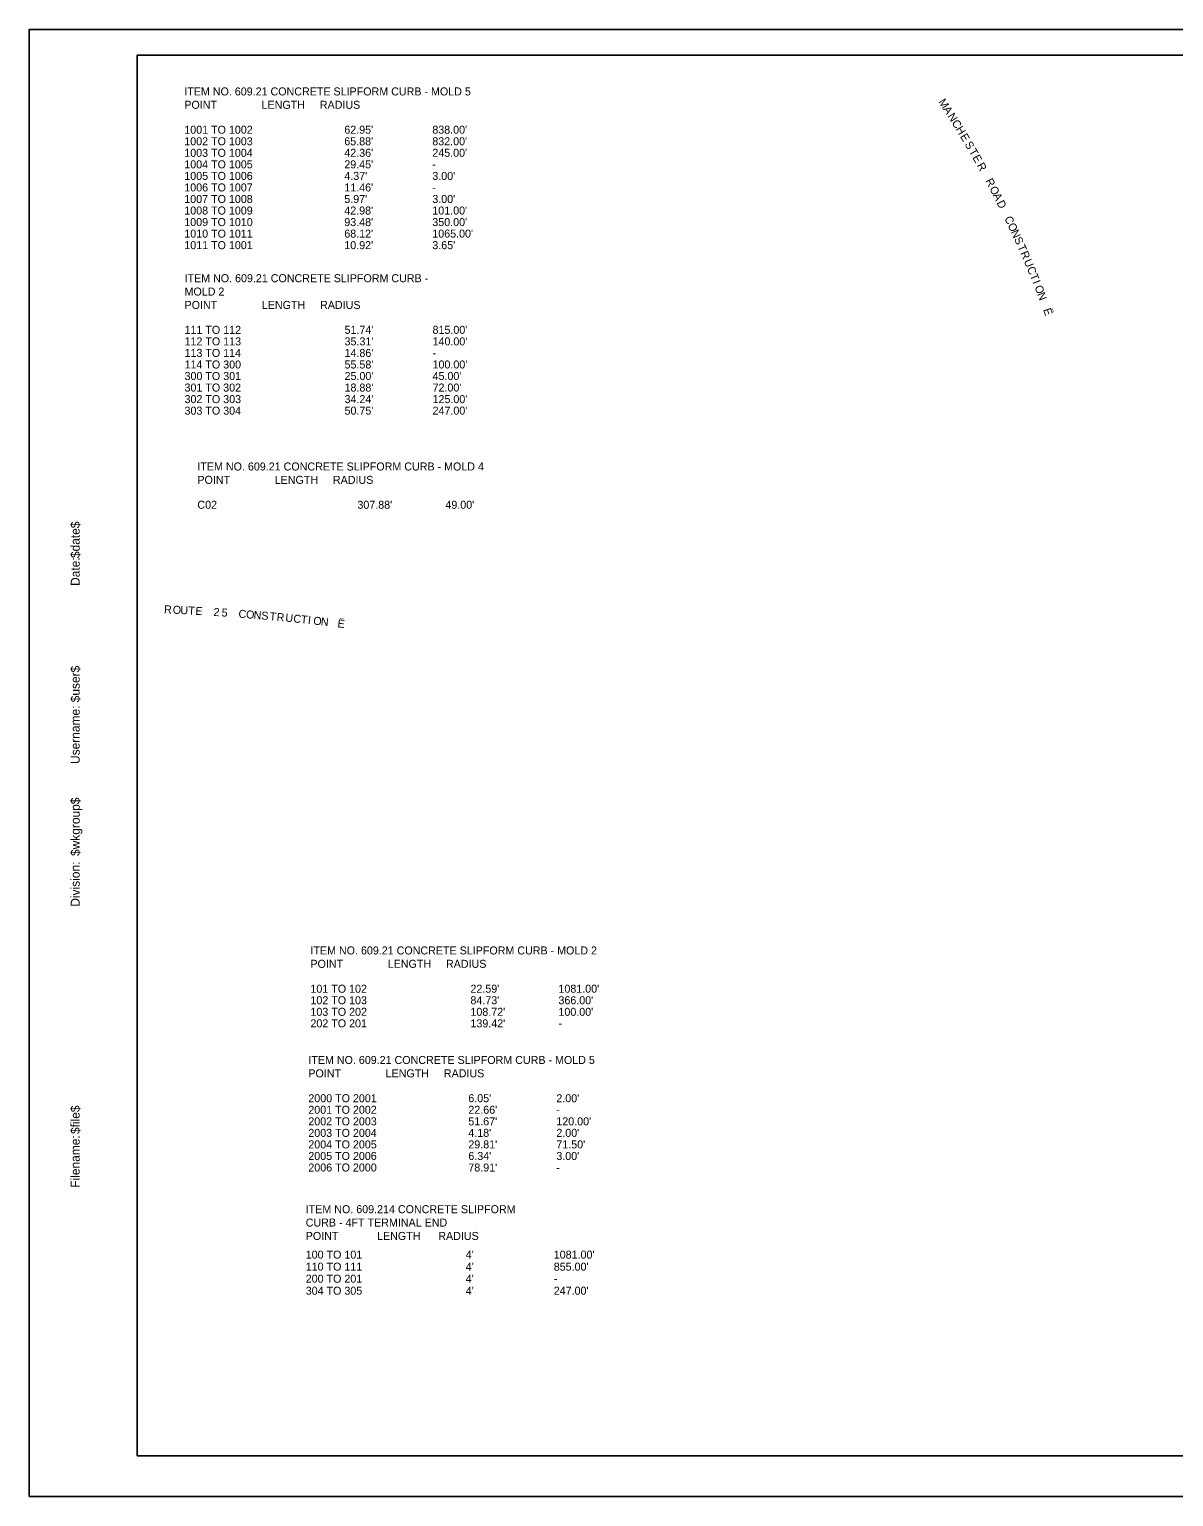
# Model space of a CAD drawing. Extents: x 916257 to 917115, y 329394 to 329944.
# Drawn here: x 916257 to 916686, y 329394 to 329944 of the extents above; entities that cross this region are included whole.
import ezdxf

# ---------------------------------------------------------------- set-up
doc = ezdxf.new("R2010")
doc.units = 0
for name, color, linetype in [('ANNOTATION', 7, 'Continuous'), ('D_Curb_Type1_Lt', 7, 'Continuous'), ('D_Roadway_Edge_Pavement', 7, 'Continuous')]:
    doc.layers.add(name, color=color, linetype=linetype)

msp = doc.modelspace()

# ---------------------------------------------------------------- linework, layer by layer
at = {"layer": 'D_Curb_Type1_Lt'}
msp.add_lwpolyline([(916257, 329393.91), (917107, 329393.91), (917107, 329943.91), (916257, 329943.91)], close=True, dxfattribs=at)
at = {"layer": 'D_Roadway_Edge_Pavement'}
for p, q in [((917097.47, 329934.21), (916297.47, 329934.21)), ((916297.47, 329934.21), (916297.47, 329409.21)), ((916297.47, 329409.21), (917097.47, 329409.21))]:
    msp.add_line(p, q, dxfattribs=at)

# ---------------------------------------------------------------- texts
at = {"layer": 'ANNOTATION'}
for s, rotation, p in [('POINT               LENGTH     RADIUS', 0.0011, (916315.11, 329914.13)), ('ITEM NO. 609.21 CONCRETE SLIPFORM CURB - MOLD 5', 0.0011, (916315.11, 329919.14)), ('M', 303.1172, (916597.75, 329916.7)), ('A', 302.6288, (916599.53, 329913.98)), ('N', 302.1668, (916601.19, 329911.38)), ('1001 TO 1002', 0.0011, (916315.11, 329904.79)), ("62.95'", 0.0011, (916375.11, 329904.79)), ("838.00'", 0.0011, (916408.11, 329904.79)), ('C', 301.7328, (916602.74, 329908.93)), ('H', 301.3073, (916604.23, 329906.52)), ('1002 TO 1003', 0.0011, (916315.11, 329900.46)), ("65.88'", 0.0011, (916375.11, 329900.46)), ("832.00'", 0.0011, (916408.11, 329900.46)), ('E', 300.8239, (916605.9, 329903.77)), ('S', 300.318, (916607.63, 329900.87)), ('1003 TO 1004', 0.0011, (916315.11, 329896.13)), ('1004 TO 1005', 0.0011, (916315.11, 329891.81)), ("42.36'", 0.0011, (916375.11, 329896.14)), ("29.45'", 0.0011, (916375.11, 329891.81)), ("245.00'", 0.0011, (916408.11, 329896.14)), ('T', 299.8525, (916609.2, 329898.19)), ('E', 299.4521, (916610.53, 329895.88)), ('1005 TO 1006', 0.0011, (916315.11, 329887.48)), ("4.37'", 0.0011, (916375.11, 329887.48)), ("3.00'", 0.0011, (916408.11, 329887.48)), ('-', 0.0011, (916408.11, 329891.81)), ('R', 298.9463, (916612.19, 329892.94)), ('1006 TO 1007', 0.0011, (916315.11, 329883.15)), ("11.46'", 0.0011, (916375.11, 329883.15)), ('-', 0.0011, (916408.11, 329883.15)), ('R', 297.9465, (916615.39, 329887.09)), ('O', 297.4567, (916616.92, 329884.21)), ('1007 TO 1008', 0.0011, (916315.11, 329878.83)), ("5.97'", 0.0011, (916375.11, 329878.83)), ("3.00'", 0.0011, (916408.11, 329878.83)), ('A', 297.0312, (916618.23, 329881.69)), ('D', 296.5692, (916619.63, 329878.95)), ('1008 TO 1009', 0.0011, (916315.11, 329874.5)), ('1009 TO 1010', 0.0011, (916315.11, 329870.17)), ("42.98'", 0.0011, (916375.11, 329874.5)), ("93.48'", 0.0011, (916375.11, 329870.17)), ("350.00'", 0.0011, (916408.11, 329870.17)), ("101.00'", 0.0011, (916408.11, 329874.5)), ('C', 295.5855, (916622.54, 329873.07)), ('1010 TO 1011', 0.0011, (916315.11, 329865.84)), ("68.12'", 0.0011, (916375.11, 329865.85)), ("1065.00'", 0.0011, (916408.11, 329865.85)), ('O', 295.16, (916623.76, 329870.51)), ('N', 294.7346, (916624.97, 329867.95)), ('1011 TO 1001', 0.0011, (916315.11, 329861.52)), ("10.92'", 0.0011, (916375.11, 329861.52)), ("3.65'", 0.0011, (916408.11, 329861.52)), ('S', 294.3005, (916626.18, 329865.32)), ('T', 293.835, (916627.46, 329862.49)), ('R', 293.4346, (916628.54, 329860.05)), ('U', 292.9448, (916629.84, 329857.05)), ('ITEM NO. 609.21 CONCRETE SLIPFORM CURB -', 0.0011, (916315.2, 329849.13)), ('C', 292.4953, (916631.01, 329854.29)), ('T', 292.0698, (916632.09, 329851.67)), ('MOLD 2', 0.0011, (916315.2, 329844.12)), ('I', 291.6694, (916633.1, 329849.2)), ('O', 291.3668, (916633.85, 329847.33)), ('N', 290.9413, (916634.88, 329844.68)), ('POINT               LENGTH     RADIUS', 0.0011, (916315.2, 329839.11)), ('Ë', 289.9974, (916637.11, 329838.8)), ('111 TO 112', 0.0011, (916315.2, 329829.78)), ("51.74'", 0.0011, (916375.2, 329829.78)), ("815.00'", 0.0011, (916408.2, 329829.78)), ('112 TO 113', 0.0011, (916315.2, 329825.45)), ('113 TO 114', 0.0011, (916315.2, 329821.12)), ("35.31'", 0.0011, (916375.2, 329825.45)), ("14.86'", 0.0011, (916375.2, 329821.12)), ("140.00'", 0.0011, (916408.2, 329825.45)), ('114 TO 300', 0.0011, (916315.2, 329816.79)), ("55.58'", 0.0011, (916375.2, 329816.79)), ('-', 0.0011, (916408.2, 329821.12)), ("100.00'", 0.0011, (916408.2, 329816.8)), ('300 TO 301', 0.0011, (916315.2, 329812.47)), ("25.00'", 0.0011, (916375.2, 329812.47)), ("45.00'", 0.0011, (916408.2, 329812.47)), ('301 TO 302', 0.0011, (916315.2, 329808.14)), ('302 TO 303', 0.0011, (916315.2, 329803.81)), ("34.24'", 0.0011, (916375.2, 329803.81)), ("18.88'", 0.0011, (916375.2, 329808.14)), ("72.00'", 0.0011, (916408.2, 329808.14)), ("125.00'", 0.0011, (916408.2, 329803.81)), ('303 TO 304', 0.0011, (916315.2, 329799.49)), ("50.75'", 0.0011, (916375.2, 329799.49)), ("247.00'", 0.0011, (916408.2, 329799.49)), ('ITEM NO. 609.21 CONCRETE SLIPFORM CURB - MOLD 4', 0.0011, (916320.02, 329778.56)), ('POINT               LENGTH     RADIUS', 0.0011, (916320.02, 329773.55)), ('C02', 0.0011, (916320.02, 329764.21)), ("307.88'", 0.0011, (916380.02, 329764.21)), ("49.00'", 0.0011, (916413.02, 329764.21)), ('R', 357.5179, (916307.46, 329725.04)), ('O', 357.2944, (916310.73, 329724.9)), ('U', 357.1002, (916313.56, 329724.77)), ('T', 356.895, (916316.55, 329724.62)), ('E', 356.7123, (916319.22, 329724.47)), ('2', 356.2487, (916325.98, 329724.07)), ('5', 356.0399, (916329.02, 329723.87)), ('C', 355.6056, (916335.35, 329723.42)), ('O', 355.4114, (916338.18, 329723.2)), ('N', 355.2172, (916341.01, 329722.98)), ('S', 355.0191, (916343.89, 329722.74)), ('T', 354.8066, (916346.98, 329722.47)), ('R', 354.6239, (916349.64, 329722.23)), ('U', 354.4004, (916352.89, 329721.92)), ('C', 354.1952, (916355.88, 329721.63)), ('T', 354.001, (916358.7, 329721.34)), ('I', 353.8183, (916361.35, 329721.07)), ('O', 353.6802, (916363.36, 329720.85)), ('N', 353.486, (916366.18, 329720.54)), ('Ë', 353.0552, (916372.43, 329719.81)), ('ITEM NO. 609.21 CONCRETE SLIPFORM CURB - MOLD 2', 0.0011, (916362.41, 329597.15)), ('POINT               LENGTH     RADIUS', 0.0011, (916362.41, 329592.14)), ('101 TO 102', 0.0011, (916362.41, 329582.8)), ('102 TO 103', 0.0011, (916362.41, 329578.48)), ("84.73'", 0.0011, (916422.41, 329578.48)), ("22.59'", 0.0011, (916422.41, 329582.81)), ("366.00'", 0.0011, (916455.41, 329578.48)), ("1081.00'", 0.0011, (916455.41, 329582.81)), ('103 TO 202', 0.0011, (916362.41, 329574.15)), ("108.72'", 0.0011, (916422.41, 329574.15)), ("100.00'", 0.0011, (916455.41, 329574.15)), ('202 TO 201', 0.0011, (916362.41, 329569.82)), ("139.42'", 0.0011, (916422.41, 329569.82)), ('-', 0.0011, (916455.41, 329569.82)), ('POINT               LENGTH     RADIUS', 0.0011, (916361.62, 329551.09)), ('ITEM NO. 609.21 CONCRETE SLIPFORM CURB - MOLD 5', 0.0011, (916361.62, 329556.1)), ('2000 TO 2001', 0.0011, (916361.62, 329541.76)), ("6.05'", 0.0011, (916421.62, 329541.76)), ("2.00'", 0.0011, (916454.62, 329541.76)), ('2001 TO 2002', 0.0011, (916361.62, 329537.43)), ("22.66'", 0.0011, (916421.62, 329537.43)), ('-', 0.0011, (916454.62, 329537.43)), ('2002 TO 2003', 0.0011, (916361.62, 329533.1)), ("51.67'", 0.0011, (916421.62, 329533.1)), ("120.00'", 0.0011, (916454.62, 329533.1)), ('2003 TO 2004', 0.0011, (916361.62, 329528.77)), ('2004 TO 2005', 0.0011, (916361.62, 329524.45)), ("4.18'", 0.0011, (916421.62, 329528.78)), ("29.81'", 0.0011, (916421.62, 329524.45)), ("2.00'", 0.0011, (916454.62, 329528.78)), ("71.50'", 0.0011, (916454.62, 329524.45)), ('2005 TO 2006', 0.0011, (916361.62, 329520.12)), ("6.34'", 0.0011, (916421.62, 329520.12)), ("3.00'", 0.0011, (916454.62, 329520.12)), ('2006 TO 2000', 0.0011, (916361.62, 329515.79)), ("78.91'", 0.0011, (916421.62, 329515.79)), ('-', 0.0011, (916454.62, 329515.79)), ('ITEM NO. 609.214 CONCRETE SLIPFORM', 0.0011, (916360.65, 329500.16)), ('CURB - 4FT TERMINAL END', 0.0011, (916360.65, 329495.15)), ('POINT             LENGTH      RADIUS', 0.0011, (916360.65, 329490.14)), ('100 TO 101', 0.0011, (916360.65, 329483.13)), ("4'", 0.0011, (916420.65, 329483.13)), ("1081.00'", 0.0011, (916453.65, 329483.14)), ('200 TO 201', 0.0011, (916360.65, 329474.12)), ('110 TO 111', 0.0011, (916360.65, 329478.63)), ("4'", 0.0011, (916420.65, 329478.63)), ("4'", 0.0011, (916420.65, 329474.12)), ("855.00'", 0.0011, (916453.65, 329478.63)), ('304 TO 305', 0.0011, (916360.65, 329469.61)), ("4'", 0.0011, (916420.65, 329469.61)), ('-', 0.0011, (916453.65, 329474.12)), ("247.00'", 0.0011, (916453.65, 329469.61))]:
    msp.add_text(s, height=3, rotation=rotation, dxfattribs=at).set_placement(p)
at = {"layer": 'D_Roadway_Edge_Pavement'}
for s, p in [('$date$', (916275.89, 329745.73)), ('Date:', (916275.89, 329735.29)), ('$user$', (916275.89, 329691.67)), ('Username:', (916275.89, 329668.55)), ('$wkgroup$', (916275.89, 329634.06)), ('Division:', (916275.89, 329615.04)), ('$file$', (916275.89, 329529.84)), ('Filename:', (916275.89, 329509.7))]:
    msp.add_text(s, height=3.348, rotation=90, dxfattribs=at).set_placement(p)

doc.saveas('drawing.dxf')
